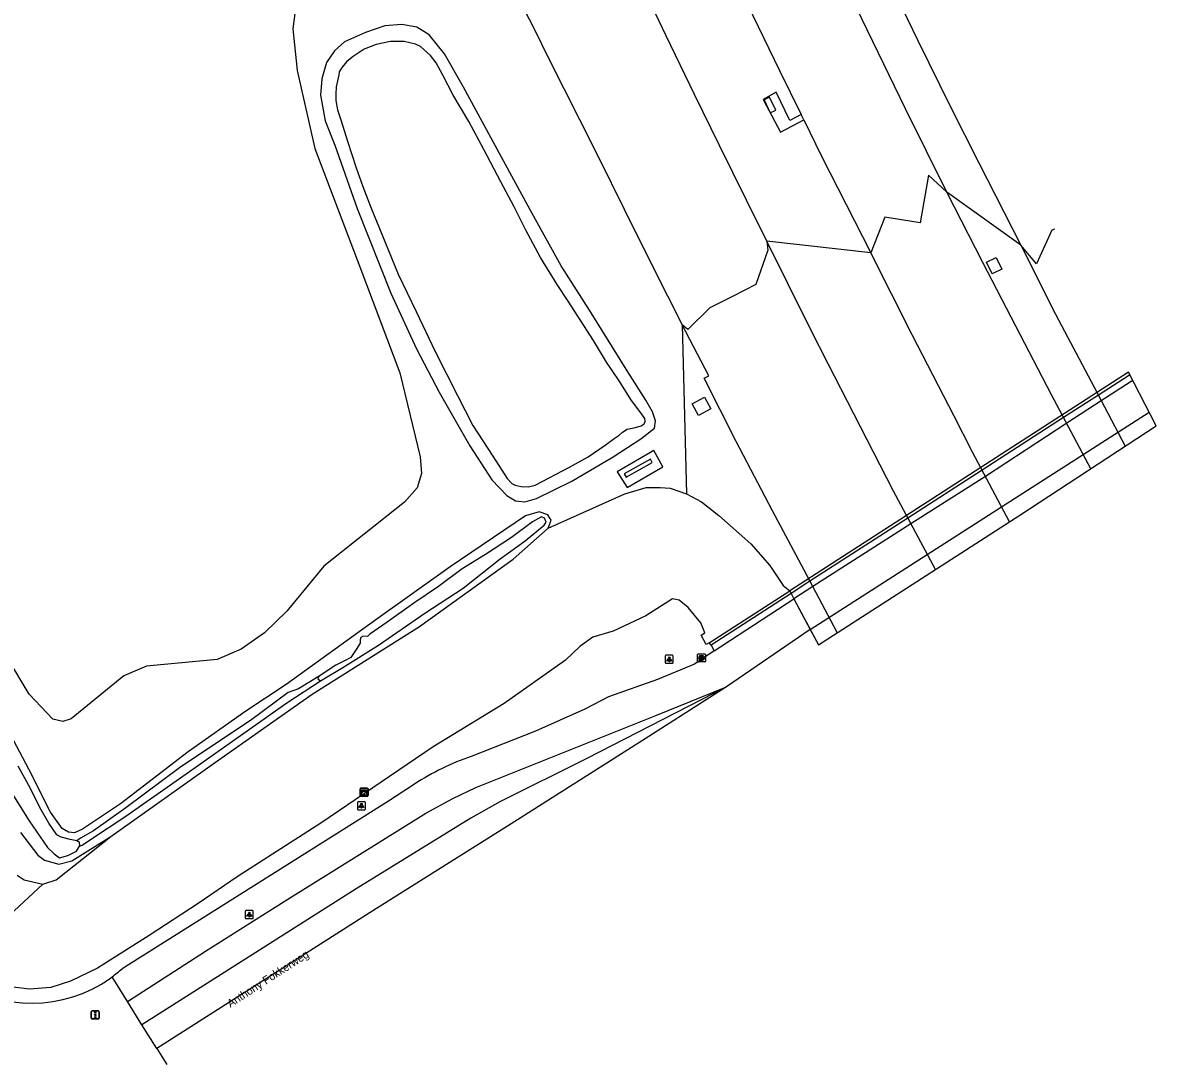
# Model space of a CAD drawing. Extents: x 155209 to 156823, y 385356 to 388482.
# Drawn here: x 156377.7 to 156519.3, y 385571 to 385701.2 of the extents above; entities that cross this region are included whole.
import ezdxf

# ---------------------------------------------------------------- set-up
doc = ezdxf.new("R2010")
doc.units = 0
for name, color, linetype in [('IMGEO_Berm_groen', 7, 'Continuous'), ('IMGEO_Berm_open', 7, 'Continuous'), ('IMGEO_Dek', 7, 'Continuous'), ('IMGEO_Grasland_overig', 7, 'Continuous'), ('IMGEO_Groenvoorziening', 7, 'Continuous'), ('IMGEO_Kast', 7, 'Continuous'), ('IMGEO_Kolk', 7, 'Continuous'), ('IMGEO_Lichtpunt', 7, 'Continuous'), ('IMGEO_Meer_plas_ven_vijver', 7, 'Continuous'), ('IMGEO_Muur', 7, 'Continuous'), ('IMGEO_Openbare_ruimte_label', 7, 'Continuous'), ('IMGEO_Rijbaan_autosnelweg', 7, 'Continuous'), ('IMGEO_Rijbaan_autoweg', 7, 'Continuous'), ('IMGEO_Rijbaan_regionaal_gesloten', 7, 'Continuous'), ('IMGEO_Terreindeel_gesloten', 7, 'Continuous'), ('IMGEO_Terreindeel_open', 7, 'Continuous'), ('IMGEO_Verkeersregelinstallatiepaal', 7, 'Continuous'), ('IMGEO_Waterloop', 7, 'Continuous')]:
    doc.layers.add(name, color=color, linetype=linetype)

msp = doc.modelspace()

# ---------------------------------------------------------------- linework, layer by layer
at = {"layer": 'IMGEO_Berm_groen'}
for points in [[(156411.76, 385703.01), (156411.42, 385700.42), (156411.95, 385695.2), (156414.17, 385685.46), (156419.8, 385670.67), (156424.77, 385657.42), (156427.32, 385646.91), (156427.51, 385644.84), (156426.94, 385643.03), (156425.36, 385641.25), (156415.27, 385633.23), (156410.67, 385627.64), (156407.86, 385624.92), (156404.95, 385622.85), (156401.94, 385621.58), (156393.13, 385620.76), (156390.29, 385619.54), (156383.72, 385614.18), (156382.68, 385613.82), (156381.42, 385614.14), (156378.46, 385617.24), (156370.43, 385630.64)], [(156453.29, 385657.53), (156448.47, 385665.23), (156444.95, 385670.78), (156441.32, 385677.33), (156437.49, 385684.37), (156432.73, 385693.12), (156430.36, 385697.28), (156428.45, 385699.67), (156426.89, 385700.6), (156425.02, 385700.94), (156422.89, 385700.78), (156420.49, 385699.97), (156417.85, 385698.78), (156416.61, 385697.68), (156415.63, 385696.21), (156415.05, 385694.16), (156414.88, 385692.1), (156415.47, 385688.93), (156416.68, 385685.85), (156419.44, 385677.95), (156423.64, 385667.39), (156426.86, 385660.41), (156429.69, 385654.99), (156433.53, 385648.28), (156436.28, 385644.03), (156438.15, 385642.07), (156439.22, 385641.4), (156440.4, 385641.28), (156441.86, 385641.69), (156446.28, 385643.86), (156451.45, 385646.92), (156454.89, 385649.17), (156456.59, 385650.51), (156456.72, 385651.41), (156456.37, 385652.54), (156455.51, 385653.99), (156453.29, 385657.53)], [(156474.93, 385689.69), (156473.51, 385688.94), (156471.79, 385692.48), (156470.17, 385691.59), (156472.36, 385687.48), (156475.25, 385689.04)], [(156502.37, 385673.36), (156493.15, 385679.99)], [(156483.62, 385672.4), (156470.64, 385673.85)], [(156498.79, 385669.79), (156498.08, 385671.25), (156499.29, 385671.84), (156500, 385670.38), (156498.79, 385669.79)], [(156460.05, 385663.43), (156460.62, 385642.27)], [(156462.09, 385652.08), (156461.32, 385653.53), (156462.86, 385654.35), (156463.64, 385652.91), (156462.09, 385652.08)], [(156451.94, 385645.04), (156453.2, 385643.08), (156457.65, 385645.66), (156456.54, 385647.69), (156451.94, 385645.04)], [(156443.31, 385637.98), (156452.88, 385642.27), (156455.58, 385643.06), (156457.32, 385643.08), (156458.56, 385642.99), (156460.62, 385642.27)], [(156460.62, 385642.27), (156462.47, 385641.27), (156464.63, 385639.56), (156468.66, 385636.02), (156471.01, 385633.33), (156472.7, 385630.81), (156473.51, 385630.15)], [(156443.31, 385637.98), (156443.69, 385639.01), (156443.27, 385639.66), (156442.2, 385640.05), (156440.49, 385639.54), (156431.09, 385633.16), (156421.79, 385626.54), (156410.6, 385618.44), (156405.55, 385615.1), (156398.33, 385610.03), (156389.86, 385603.52), (156385.11, 385600.35), (156384.14, 385599.93), (156383.37, 385600), (156382.6, 385600.44), (156381.15, 385602.5), (156378.43, 385607.89), (156372.36, 385619.28)], [(156463.43, 385623.66), (156463.05, 385623.44), (156462.44, 385624.64), (156462.88, 385624.9), (156462.38, 385626.16), (156460.81, 385628.06), (156459.67, 385629), (156458.85, 385629.15), (156455.51, 385627.05), (156451.42, 385625.11), (156448.9, 385624.38), (156447.27, 385623.22), (156445.49, 385621.51), (156437.83, 385616.06), (156428.96, 385610.68), (156414.93, 385601.13), (156404.47, 385594.43), (156399.59, 385591.09), (156393.45, 385587.09), (156387.8, 385583.51), (156387, 385583.01), (156383.65, 385581.35), (156381.18, 385580.56), (156378.51, 385580.38), (156376.47, 385580.62)], [(156377.4, 385599.97), (156379.56, 385597.1), (156380.4, 385596.48), (156382.18, 385595.98), (156383.81, 385596.41), (156388.67, 385599.44)], [(156380.16, 385593.51), (156381.83, 385594.03), (156388.67, 385599.44)], [(156376.95, 385594.63), (156377.83, 385594.03), (156380.16, 385593.51)]]:
    msp.add_lwpolyline(points, dxfattribs=at)
at = {"layer": 'IMGEO_Berm_open'}
for points in [[(156473.68, 385629.84), (156474.02, 385629.18)], [(156463.7, 385623.35), (156464.05, 385622.65)]]:
    msp.add_lwpolyline(points, dxfattribs=at)
at = {"layer": 'IMGEO_Dek'}
msp.add_lwpolyline([(156477.09, 385623.42), (156502.27, 385639.63), (156519.31, 385650.79), (156515.84, 385657.5), (156473.51, 385630.15), (156473.68, 385629.84), (156474.02, 385629.18)], close=True, dxfattribs=at)
at = {"layer": 'IMGEO_Grasland_overig'}
msp.add_lwpolyline([(156369.99, 385584.07), (156380.16, 385593.51)], dxfattribs=at)
at = {"layer": 'IMGEO_Groenvoorziening'}
msp.add_lwpolyline([(156388.67, 385599.44), (156401.74, 385608.73), (156413.82, 385617.24), (156427.26, 385625.69), (156438.93, 385634.11), (156443.31, 385637.98)], dxfattribs=at)
at = {"layer": 'IMGEO_Kast'}
for p, q in [((156419.81, 385604.55), (156419.81, 385605.4)), ((156419.81, 385605.4), (156419.81, 385604.55)), ((156419.88, 385605.48), (156420.72, 385605.48)), ((156420.72, 385605.48), (156419.88, 385605.48)), ((156420.73, 385604.48), (156419.89, 385604.48)), ((156419.89, 385604.48), (156420.73, 385604.48)), ((156420.81, 385605.41), (156420.81, 385604.56)), ((156420.81, 385604.56), (156420.81, 385605.41))]:
    msp.add_line(p, q, dxfattribs=at)
for points in [[(156420, 385605.27), (156420.6, 385605.27), (156420.6, 385605.18), (156420, 385605.18), (156420, 385605.27)], [(156420, 385605.1), (156420.6, 385605.1), (156420.6, 385604.61), (156420, 385604.61), (156420, 385605.1)]]:
    msp.add_lwpolyline(points, dxfattribs=at)
msp.add_circle((156420.09, 385604.94), 0.0377, dxfattribs=at)
for centre, start, end in [((156419.89, 385605.4), 92.4484, 184.2845), ((156419.89, 385605.4), 92.4484, 184.2845), ((156419.89, 385604.56), 182.4484, 274.2845), ((156419.89, 385604.56), 182.4484, 274.2845), ((156420.73, 385605.4), 2.4484, 94.2845), ((156420.73, 385605.4), 2.4484, 94.2845), ((156420.73, 385604.56), 272.4484, 4.2845), ((156420.73, 385604.56), 272.4484, 4.2845)]:
    msp.add_arc(centre, 0.0779, start, end, dxfattribs=at)
at = {"layer": 'IMGEO_Kolk'}
for p, q in [((156461.98, 385621.35), (156461.98, 385622.2)), ((156462.05, 385622.28), (156462.91, 385622.28)), ((156462.91, 385621.28), (156462.05, 385621.28)), ((156462.49, 385621.5), (156462.46, 385621.5)), ((156462.47, 385622.06), (156462.49, 385622.06)), ((156462.98, 385622.2), (156462.98, 385621.35))]:
    msp.add_line(p, q, dxfattribs=at)
for points in [[(156461.98, 385621.35), (156461.98, 385622.2)], [(156462.05, 385622.28), (156462.91, 385622.28)], [(156462.91, 385621.28), (156462.05, 385621.28)], [(156462.3, 385621.98), (156462.42, 385621.98), (156462.42, 385621.82), (156462.55, 385621.98), (156462.72, 385621.98), (156462.57, 385621.83), (156462.72, 385621.58), (156462.57, 385621.58), (156462.49, 385621.74), (156462.42, 385621.67), (156462.42, 385621.58), (156462.3, 385621.58), (156462.3, 385621.98)], [(156462.98, 385622.2), (156462.98, 385621.35)]]:
    msp.add_lwpolyline(points, dxfattribs=at)
for centre, start, end in [((156462.06, 385622.2), 91.552, 178.448), ((156462.06, 385622.2), 91.552, 178.448), ((156462.06, 385621.35), 181.552, 268.448), ((156462.06, 385621.35), 181.552, 268.448), ((156462.9, 385622.2), 1.552, 88.448), ((156462.9, 385622.2), 1.552, 88.448), ((156462.9, 385621.35), 271.552, 358.448), ((156462.9, 385621.35), 271.552, 358.448)]:
    msp.add_arc(centre, 0.0765, start, end, dxfattribs=at)
for centre, major_axis, ratio, start_param, end_param in [((156462.47, 385621.78), (-0.387, 0.002), 0.722429, 4.712389, 7.853982), ((156462.49, 385621.78), (-0.39, 0.002), 0.717154, 1.570796, 4.712389)]:
    msp.add_ellipse(centre, major_axis=major_axis, ratio=ratio, start_param=start_param, end_param=end_param, dxfattribs=at)
at = {"layer": 'IMGEO_Lichtpunt'}
for p, q in [((156457.95, 385622.01), (156457.95, 385621.2)), ((156457.95, 385622.01), (156457.95, 385621.2)), ((156458.85, 385622.1), (156458.04, 385622.1)), ((156458.85, 385622.1), (156458.04, 385622.1)), ((156458.04, 385621.1), (156458.85, 385621.1)), ((156458.04, 385621.1), (156458.85, 385621.1)), ((156458.95, 385621.2), (156458.95, 385622.01)), ((156458.95, 385621.2), (156458.95, 385622.01)), ((156419.49, 385603.69), (156419.49, 385602.88)), ((156419.49, 385603.69), (156419.49, 385602.88)), ((156420.39, 385603.78), (156419.58, 385603.78)), ((156420.39, 385603.78), (156419.58, 385603.78)), ((156419.58, 385602.79), (156420.39, 385602.79)), ((156419.58, 385602.79), (156420.39, 385602.79)), ((156420.48, 385602.88), (156420.48, 385603.69)), ((156420.48, 385602.88), (156420.48, 385603.69)), ((156405.47, 385590.09), (156405.47, 385589.28)), ((156405.47, 385590.09), (156405.47, 385589.28)), ((156406.37, 385590.19), (156405.56, 385590.19)), ((156406.37, 385590.19), (156405.56, 385590.19)), ((156406.46, 385589.28), (156406.46, 385590.09)), ((156406.46, 385589.28), (156406.46, 385590.09)), ((156405.56, 385589.19), (156406.37, 385589.19)), ((156405.56, 385589.19), (156406.37, 385589.19))]:
    msp.add_line(p, q, dxfattribs=at)
for points in [[(156458.32, 385621.67), (156458.36, 385621.64), (156458.18, 385621.38), (156458.14, 385621.41), (156458.32, 385621.67)], [(156458.43, 385621.62), (156458.47, 385621.62), (156458.47, 385621.3), (156458.43, 385621.3), (156458.43, 385621.62)], [(156458.54, 385621.64), (156458.57, 385621.67), (156458.76, 385621.41), (156458.72, 385621.38), (156458.54, 385621.64)], [(156419.86, 385603.35), (156419.9, 385603.32), (156419.71, 385603.06), (156419.67, 385603.09), (156419.86, 385603.35)], [(156419.96, 385603.3), (156420.01, 385603.3), (156420.01, 385602.98), (156419.96, 385602.98), (156419.96, 385603.3)], [(156420.07, 385603.32), (156420.11, 385603.35), (156420.3, 385603.09), (156420.26, 385603.06), (156420.07, 385603.32)], [(156405.84, 385589.75), (156405.88, 385589.73), (156405.69, 385589.46), (156405.65, 385589.49), (156405.84, 385589.75)], [(156405.94, 385589.71), (156405.99, 385589.71), (156405.99, 385589.38), (156405.94, 385589.38), (156405.94, 385589.71)], [(156406.05, 385589.73), (156406.09, 385589.75), (156406.28, 385589.49), (156406.24, 385589.46), (156406.05, 385589.73)]]:
    msp.add_lwpolyline(points, dxfattribs=at)
for centre in [(156458.45, 385621.8), (156419.99, 385603.49), (156405.97, 385589.89)]:
    msp.add_circle(centre, 0.0994, dxfattribs=at)
for centre, start, end in [((156458.04, 385622.01), 90, 180), ((156458.04, 385622.01), 90, 180), ((156458.04, 385621.2), 180, 270), ((156458.04, 385621.2), 180, 270), ((156458.85, 385622.01), 0, 90), ((156458.85, 385622.01), 0, 90), ((156458.85, 385621.2), 270, 0), ((156458.85, 385621.2), 270, 360), ((156419.58, 385603.69), 90, 180), ((156419.58, 385603.69), 90, 180), ((156419.58, 385602.88), 180, 270), ((156419.58, 385602.88), 180, 270), ((156420.39, 385603.69), 0, 90), ((156420.39, 385603.69), 0, 90), ((156420.39, 385602.88), 270, 0), ((156420.39, 385602.88), 270, 360), ((156405.56, 385590.09), 90, 180), ((156405.56, 385590.09), 90, 180), ((156406.37, 385590.09), 0, 90), ((156406.37, 385590.09), 0, 90), ((156405.56, 385589.28), 180, 270), ((156405.56, 385589.28), 180, 270), ((156406.37, 385589.28), 270, 0), ((156406.37, 385589.28), 270, 360)]:
    msp.add_arc(centre, 0.0946, start, end, dxfattribs=at)
at = {"layer": 'IMGEO_Meer_plas_ven_vijver'}
msp.add_lwpolyline([(156421.21, 385677.99), (156422.52, 385674.73), (156424.58, 385669.73), (156426.83, 385665.09), (156429.19, 385660.07), (156431.97, 385654.58), (156433.92, 385650.83), (156436.4, 385646.99), (156438.21, 385644.2), (156438.76, 385643.58), (156439.19, 385643.36), (156439.93, 385643.2), (156440.84, 385643.16), (156441.69, 385643.38), (156445.99, 385645.63), (156448.33, 385646.93), (156450.45, 385648.39), (156451.57, 385649.19), (156452.18, 385649.64), (156452.62, 385650), (156453.17, 385650.36), (156454.25, 385650.56), (156454.95, 385650.78), (156455.33, 385651.03), (156455.44, 385651.31), (156455.41, 385651.71), (156455.03, 385652.26), (156453.74, 385653.96), (156452.21, 385656.42), (156450.62, 385658.75), (156448.99, 385661.44), (156447.4, 385663.91), (156445.83, 385666.36), (156444.43, 385668.46), (156442.38, 385671.83), (156440.52, 385675.24), (156439.05, 385678.15), (156437.4, 385681.3), (156435.3, 385685.32), (156433.39, 385688.82), (156431.46, 385692.1), (156430.16, 385694.64), (156429.33, 385696.16), (156428.62, 385697.08), (156427.35, 385698.21), (156426.72, 385698.51), (156425.31, 385698.81), (156423.62, 385698.82), (156421.83, 385698.47), (156420.34, 385697.86), (156418.96, 385696.96), (156418.15, 385696.33), (156417.57, 385695.6), (156417.22, 385695.02), (156417.14, 385694.66), (156416.99, 385693.93), (156416.84, 385693.15), (156416.77, 385692.23), (156416.8, 385691.47), (156416.99, 385690.29), (156417.44, 385688.92), (156418.25, 385686.36), (156419.34, 385683.02), (156420.17, 385680.7), (156421.21, 385677.99)], dxfattribs=at)
at = {"layer": 'IMGEO_Muur'}
for points in [[(156516.01, 385657.17), (156515.82, 385657.04), (156512.07, 385654.62), (156507.72, 385651.81), (156497.54, 385645.24), (156488.26, 385639.25), (156476.03, 385631.37), (156473.68, 385629.84)], [(156463.43, 385623.66), (156473.51, 385630.15)], [(156473.68, 385629.84), (156463.7, 385623.35)], [(156473.51, 385630.15), (156473.68, 385629.84)], [(156463.7, 385623.35), (156463.43, 385623.66)]]:
    msp.add_lwpolyline(points, dxfattribs=at)
at = {"layer": 'IMGEO_Rijbaan_autosnelweg'}
for points in [[(156398.05, 385867.6), (156398.93, 385865.33), (156402.27, 385856.57), (156405.66, 385848.03), (156408.81, 385839.82), (156412.57, 385830.35), (156416.01, 385821.8), (156418.99, 385814.4), (156422.01, 385806.81), (156426.46, 385796.23), (156430.23, 385787.35), (156434.44, 385777.74), (156439.27, 385766.71), (156443.12, 385757.95), (156446.66, 385750.04), (156450.87, 385740.66), (156454.25, 385733.37), (156458.63, 385723.81), (156462.79, 385714.93), (156467.56, 385704.85), (156472.21, 385695.22), (156474.93, 385689.69)], [(156493.15, 385679.99), (156487.96, 385690.43), (156483.87, 385698.81), (156479.73, 385707.45), (156475.52, 385716.32), (156471.33, 385725.1), (156467.63, 385733.03), (156463.64, 385741.65), (156459.82, 385750.1), (156456.15, 385758.32), (156452.76, 385765.8), (156449.66, 385772.95)], [(156457.95, 385766.88), (156461.42, 385758.96), (156464.28, 385752.73), (156467.28, 385746.1), (156470.67, 385738.8), (156474.15, 385731.19), (156477.58, 385723.92), (156481.36, 385715.92), (156485.51, 385707.25), (156489.51, 385698.97), (156493.6, 385690.65), (156497.14, 385683.65), (156502.37, 385673.36)], [(156475.25, 385689.04), (156474.93, 385689.69)], [(156475.25, 385689.04), (156477.49, 385684.48), (156483.62, 385672.4)], [(156493.15, 385679.99), (156490.85, 385682.12), (156489.8, 385676.17), (156485.38, 385676.86), (156483.62, 385672.4)], [(156511.13, 385645.43), (156506.21, 385654.65), (156501.76, 385663.24), (156497.65, 385671.22), (156493.15, 385679.99)], [(156506.58, 385675.39), (156506.24, 385675.26), (156504.35, 385671.02), (156502.37, 385673.36)], [(156500.95, 385638.78), (156496.35, 385647.5), (156494.04, 385652.01), (156488.79, 385662.18), (156483.62, 385672.4)], [(156502.37, 385673.36), (156506.71, 385664.74), (156511.54, 385655.61), (156515.42, 385648.24)]]:
    msp.add_lwpolyline(points, dxfattribs=at)
at = {"layer": 'IMGEO_Rijbaan_autoweg'}
for points in [[(156470.64, 385673.85), (156468.1, 385678.99), (156464.69, 385685.93), (156461.61, 385692.21), (156458.06, 385699.54), (156454.83, 385706.36), (156450.92, 385714.55), (156447.68, 385721.47), (156444.6, 385728.13), (156441.13, 385735.58), (156437.74, 385742.98), (156434.16, 385751), (156430.54, 385759.15), (156427.88, 385765.22), (156425.2, 385771.31)], [(156440.2, 385703.07), (156441.6, 385700.31), (156443.38, 385696.75), (156447.23, 385689.06), (156449.59, 385684.37), (156452.8, 385677.86), (156456.4, 385670.65), (156460.05, 385663.43)], [(156470.64, 385673.85), (156470.77, 385672.76), (156469.27, 385668.45), (156466.37, 385666.95), (156463.52, 385665.53), (156460.77, 385662.83), (156460.05, 385663.43)], [(156491.7, 385632.83), (156486.47, 385642.6), (156481.52, 385652.27), (156478.3, 385658.52), (156476.1, 385662.89), (156473.27, 385668.58), (156470.64, 385673.85)], [(156479.45, 385624.94), (156475.3, 385632.74), (156471.37, 385640.17), (156466.83, 385648.84), (156462.8, 385656.74), (156463.38, 385657.04), (156460.05, 385663.43)]]:
    msp.add_lwpolyline(points, dxfattribs=at)
at = {"layer": 'IMGEO_Rijbaan_regionaal_gesloten'}
for points in [[(156516.38, 385656.45), (156516.18, 385656.32), (156512.44, 385653.91), (156508.11, 385651.1), (156497.95, 385644.47), (156488.65, 385638.52), (156476.39, 385630.69), (156474.02, 385629.18)], [(156476.07, 385625.34), (156518.43, 385652.49)], [(156464.05, 385622.65), (156474.02, 385629.18)], [(156474.02, 385629.18), (156476.07, 385625.34)], [(156476.07, 385625.34), (156465.6, 385618.18)], [(156476.07, 385625.34), (156477.09, 385623.42)], [(156464.05, 385622.65), (156461.6, 385621.01), (156456.96, 385619.09), (156450.84, 385616.92), (156447.89, 385615.37), (156441.74, 385612.61), (156433.71, 385609.46)], [(156390.74, 385578.81), (156400.48, 385585.11), (156410.8, 385591.61), (156428.02, 385602.36), (156431.41, 385604.21), (156434.28, 385605.58), (156456.77, 385614.59), (156465.6, 385618.18)], [(156465.6, 385618.18), (156448.14, 385609.21), (156437.27, 385603.78), (156433.67, 385601.76), (156419.31, 385592.92), (156392.56, 385575.91)], [(156465.6, 385618.18), (156455.42, 385611.65), (156438.22, 385600.76), (156421.06, 385589.94), (156394.4, 385572.97)], [(156426.63, 385606.01), (156423.35, 385603.86), (156390.07, 385582.92)], [(156390.74, 385578.81), (156388.82, 385581.91)], [(156392.56, 385575.91), (156390.74, 385578.81)], [(156394.4, 385572.97), (156392.56, 385575.91)], [(156394.4, 385572.97), (156395.65, 385570.97)]]:
    msp.add_lwpolyline(points, dxfattribs=at)
for centre, radius, start, end in [((156443.61, 385580.18), 30.91, 108.668, 123.3247), ((156378.61, 385595.74), 17.2, 306.4406, 311.8024), ((156378.83, 385595.47), 16.85, 230.8743, 300.9173), ((156379, 385595.22), 16.55, 300.8549, 306.4264)]:
    msp.add_arc(centre, radius, start, end, dxfattribs=at)
at = {"layer": 'IMGEO_Terreindeel_gesloten'}
msp.add_lwpolyline([(156456.33, 385646.22), (156456.1, 385646.63), (156452.82, 385644.79), (156453.05, 385644.37), (156456.33, 385646.22)], dxfattribs=at)
at = {"layer": 'IMGEO_Terreindeel_open'}
msp.add_lwpolyline([(156470.98, 385691.87), (156470.3, 385691.55), (156471.07, 385689.91), (156471.75, 385690.23), (156470.98, 385691.87)], dxfattribs=at)
at = {"layer": 'IMGEO_Verkeersregelinstallatiepaal'}
for p, q in [((156386.23, 385576.75), (156386.23, 385577.55)), ((156386.23, 385577.55), (156386.23, 385576.75)), ((156386.33, 385577.65), (156387.12, 385577.65)), ((156387.12, 385577.65), (156386.33, 385577.65)), ((156387.22, 385577.55), (156387.22, 385576.75)), ((156387.22, 385576.75), (156387.22, 385577.55)), ((156387.12, 385576.65), (156386.33, 385576.65)), ((156386.33, 385576.65), (156387.12, 385576.65))]:
    msp.add_line(p, q, dxfattribs=at)
for centre in [(156386.73, 385577.44), (156386.73, 385577.15), (156386.73, 385576.86)]:
    msp.add_circle(centre, 0.085, dxfattribs=at)
for centre, start, end in [((156386.33, 385577.55), 90, 180), ((156386.33, 385577.55), 90, 180), ((156387.12, 385577.55), 0, 90), ((156387.12, 385577.55), 360, 90), ((156386.33, 385576.75), 180, 270), ((156386.33, 385576.75), 180, 270), ((156387.12, 385576.75), 270, 0), ((156387.12, 385576.75), 270, 0)]:
    msp.add_arc(centre, 0.1, start, end, dxfattribs=at)
at = {"layer": 'IMGEO_Waterloop'}
for points in [[(156414.88, 385618.9), (156417.68, 385620.59), (156422.11, 385623.36), (156427.89, 385627.36), (156432.68, 385630.5), (156437.32, 385634.16), (156440.43, 385636.41), (156442.82, 385638.35), (156443.07, 385638.73), (156442.84, 385639.23), (156442.47, 385639.43), (156441.36, 385638.79), (156438.74, 385636.84), (156435.5, 385634.72), (156432.57, 385632.9), (156429.61, 385630.71), (156426.54, 385628.63), (156423.19, 385626.26), (156421.02, 385624.73), (156420.75, 385624.47), (156420.2, 385624.5), (156419.89, 385624.34), (156419.83, 385624.04), (156419.83, 385623.62), (156419.34, 385622.81), (156418.66, 385621.82), (156417.88, 385621.43), (156416.78, 385620.86), (156414.69, 385619.48)], [(156414.69, 385619.48), (156412.11, 385617.91), (156410.85, 385617.47), (156406.14, 385613.94), (156397.43, 385608.15), (156390.55, 385603.05), (156386.5, 385600.16), (156384.9, 385599.26), (156384.43, 385598.91)], [(156384.77, 385598.25), (156385.08, 385598.36), (156386.38, 385599.24), (156390.4, 385601.93), (156398.08, 385607.27), (156405.27, 385612.37), (156410.65, 385616.17), (156414.88, 385618.9)], [(156414.69, 385619.48), (156414.55, 385619.15), (156414.88, 385618.9)], [(156384.43, 385598.91), (156383.58, 385599.08), (156382.46, 385599.36), (156381.94, 385599.65), (156380.91, 385601.14), (156379.81, 385603.07), (156378.62, 385605.45), (156377.09, 385608.25)], [(156375.89, 385605.52), (156378.47, 385601.4), (156380.74, 385598.09), (156381.59, 385597.29), (156382.26, 385596.77), (156383.29, 385597.07), (156384.4, 385597.63), (156384.77, 385598.25)], [(156384.43, 385598.91), (156384.73, 385598.78), (156384.77, 385598.25)]]:
    msp.add_lwpolyline(points, dxfattribs=at)

# ---------------------------------------------------------------- texts
at = {"layer": 'IMGEO_Openbare_ruimte_label'}
msp.add_text('Anthony Fokkerweg', height=1, rotation=32.959, dxfattribs=at).set_placement((156403.61, 385578.04))

doc.saveas('drawing.dxf')
